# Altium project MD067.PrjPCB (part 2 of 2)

## Sheet MD067_INTERFACE.SchDoc
size 431 x 279 mm; Date: Not shown in title block; ApprovedBy: Not shown in title block; CheckedBy: Not shown in title block; Author: Not shown in title block; CompanyName: Not shown in title block; Engineer: Not shown in title block; Organization: Not shown in title block; Address1: Not shown in title block; Address2: Not shown in title block; Address3: Not shown in title block; Address4: Not shown in title block; DocumentNumber: 1; Revision: Use project parameter SCH_Rev; SheetNumber: 1; SheetTotal: 5; PageSetup: Record=PageOptions¦CenterHorizontal=True¦CenterVertical=True¦PrintScale=1.00¦XCorrection=1.00¦YCorrection=1.00¦PrintKind=0¦BorderSize=5000000¦LeftOffset=0¦BottomOffset=0¦Orientation=2¦PaperLength=1000¦PaperWidth=1000¦Scale=100¦PaperSource=15¦PrintQuality=600¦MediaType=1¦DitherType=10¦PaperKind=Letter¦PrintScaleMode=1
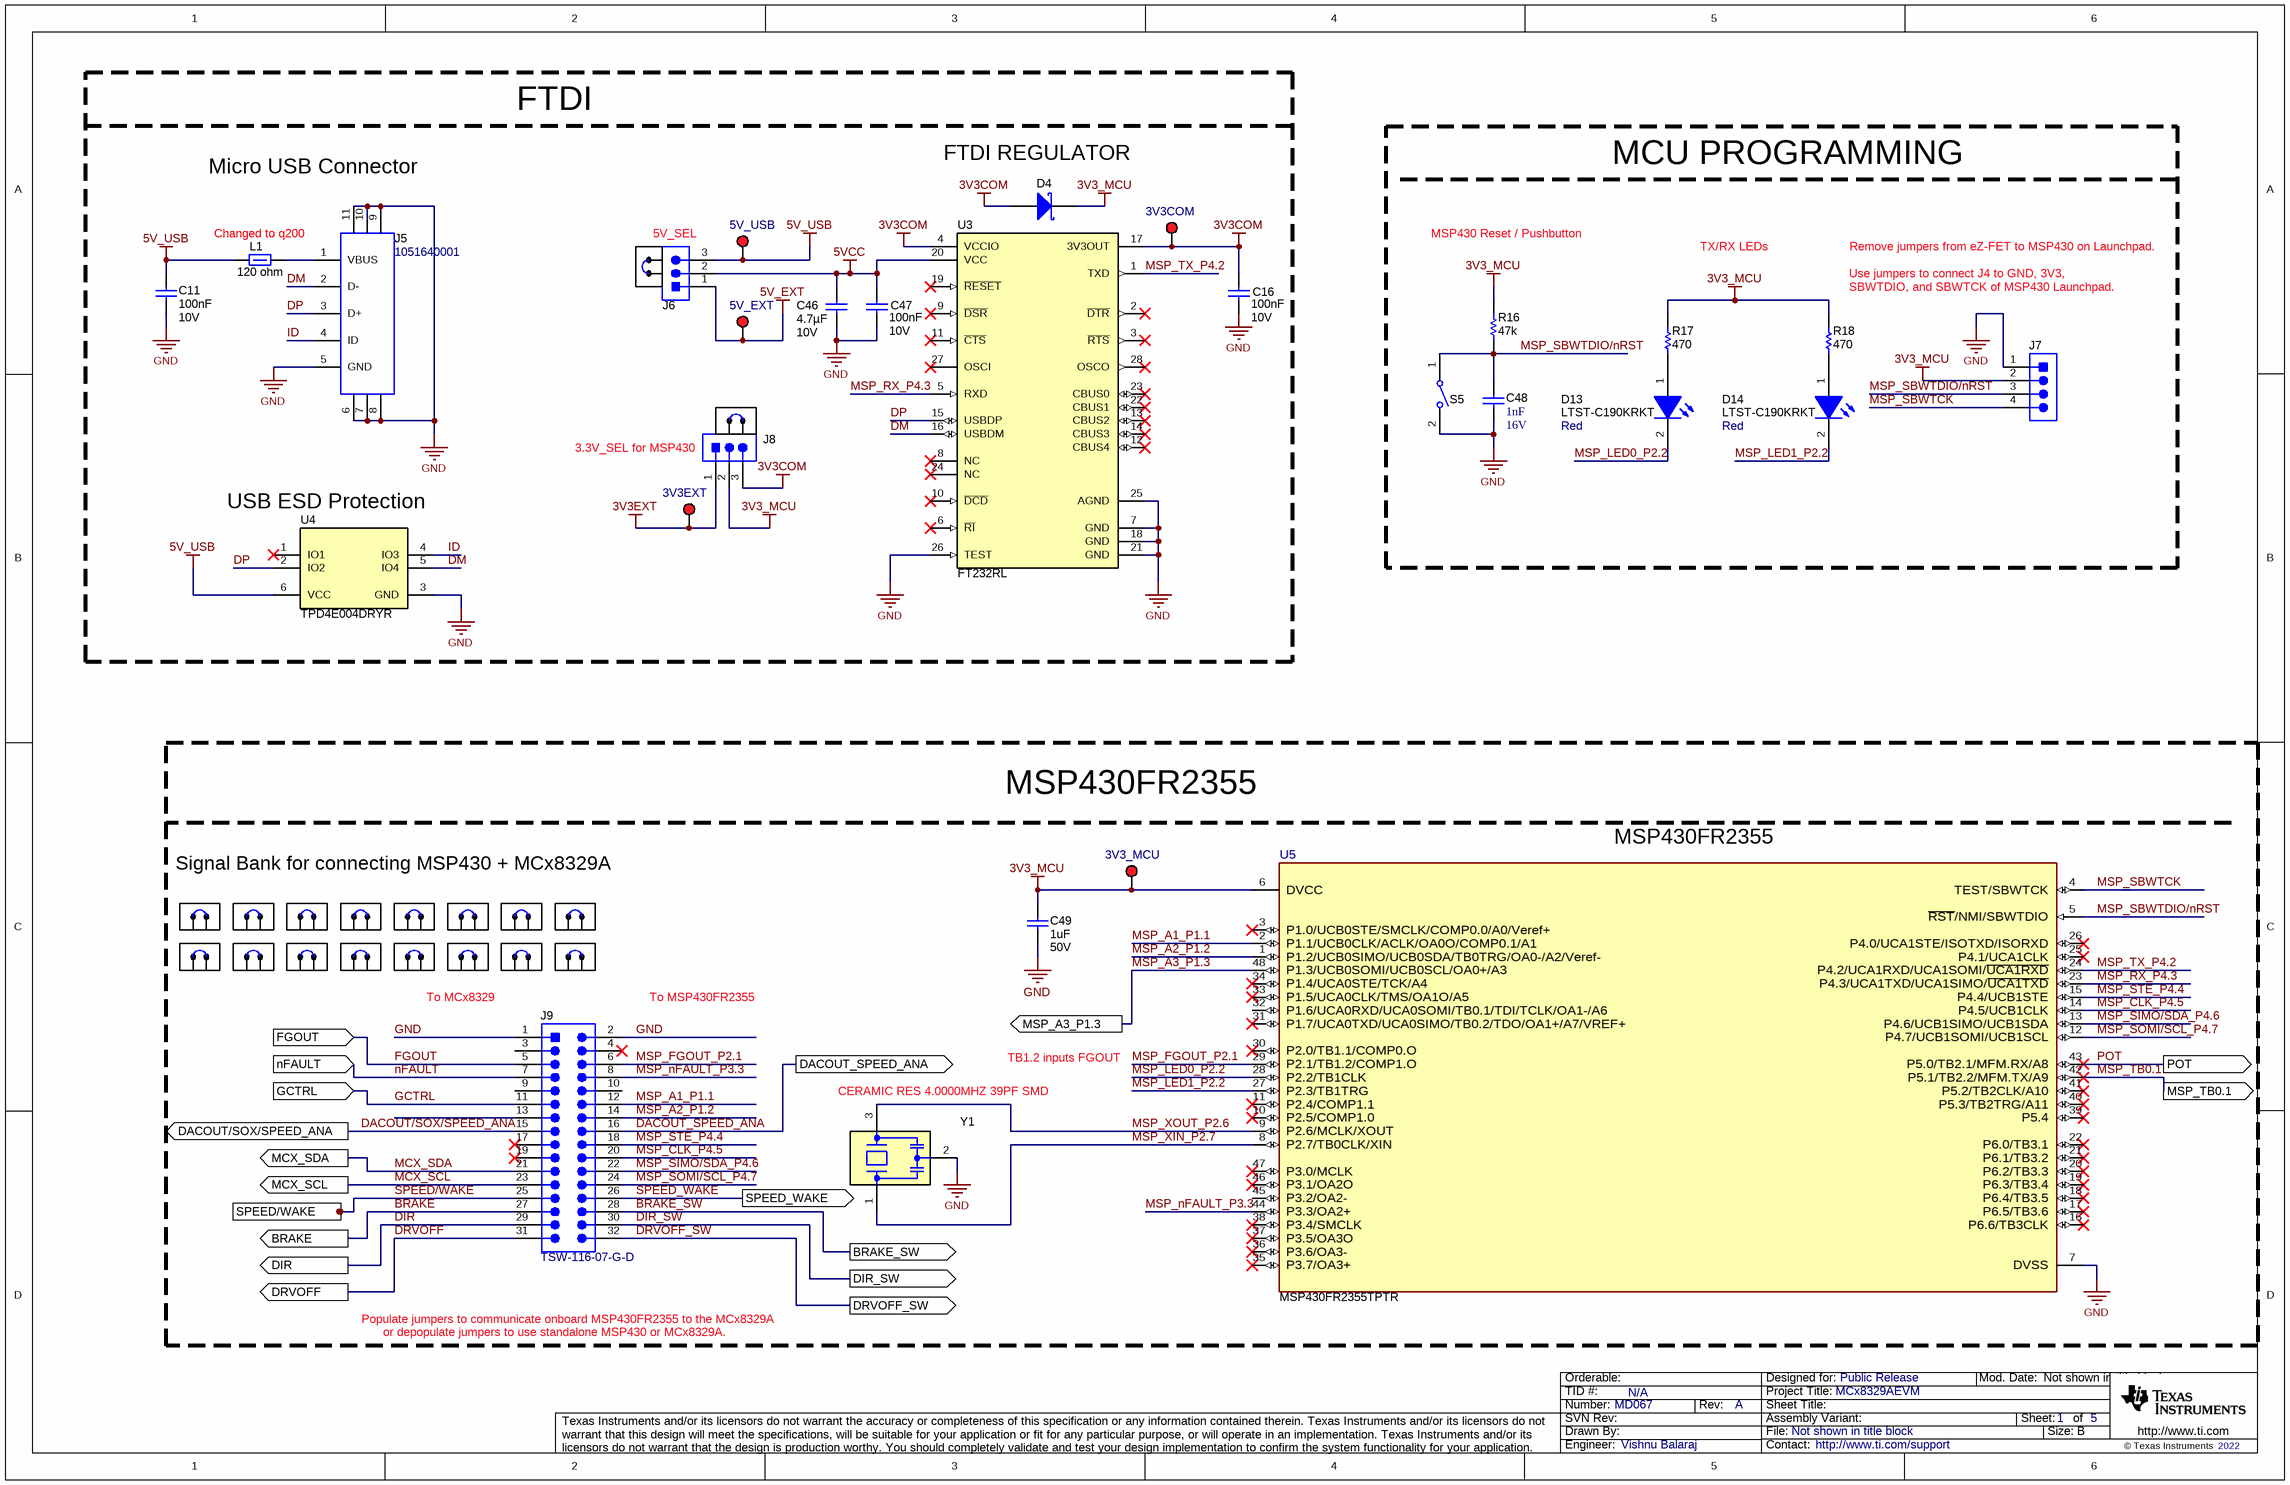
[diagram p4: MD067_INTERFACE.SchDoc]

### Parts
C11  Cap_F: 100nF  VDC_V: 10V  [0603L]  (hidden comment: 0603ZC104KAT2A)
C16  Cap_F: 100nF  VDC_V: 10V  [0603L]  (hidden comment: 0603ZC104KAT2A)
C46  Cap_F: 4.7µF  VDC_V: 10V  [0603L]  (hidden comment: GRM188Z71A475ME15D)
C47  Cap_F: 100nF  VDC_V: 10V  [0603L]  (hidden comment: 0603ZC104KAT2A)
C48  Cap_F: 1nF  VDC_V: 16V  [0603L]  (hidden comment: 885012206034)
C49  ValueDisplayed: 1uF  VDC_V: 50V  [0805L]  (hidden comment: 885012207103)
D4  BAT165E6327HTSA1  [SOD-323]  (value not drawn)
D13  LTST-C190KRKT  value Red  [LED_LTST-C190_Red]
D14  LTST-C190KRKT  value Red  [LED_LTST-C190_Red]
J5  1051640001  [Molex_1051640001]
J6  5V_SEL  [PBC03SAAN]  (value not drawn)
J7  TSW-104-07-G-S  [TSW-104-07-G-S]  (value not drawn)
J8  Header_3x1  [PBC03SAAN]  (value not drawn)
J9  TSW-116-07-G-D  [TSW-116-07-G-D]
L1  DCR_ohm: 120 ohm  [0603L]  (hidden comment: BLM18SG121TZ1D)
R16  ValueDisplayed: 47k  [0603L]  (hidden comment: RC0603JR-0747KL)
R17  ValueDisplayed: 470  [0603L]  (hidden comment: RC0603JR-07470RL)
R18  ValueDisplayed: 470  [0603L]  (hidden comment: RC0603JR-07470RL)
S5  SW_SPST-single  [SW_434121025816]  (value not drawn)
SH-J4  SNT-100-BK-G  [SNT-100-BK-G]  (value not drawn)
SH-J5  SNT-100-BK-G  [SNT-100-BK-G]  (value not drawn)
SH-J6  SNT-100-BK-G  [SNT-100-BK-G]  (value not drawn)
SH-J10  SNT-100-BK-G  [SNT-100-BK-G]  (value not drawn)
SH-J11  SNT-100-BK-G  [SNT-100-BK-G]  (value not drawn)
SH-J12  SNT-100-BK-G  [SNT-100-BK-G]  (value not drawn)
SH-J13  SNT-100-BK-G  [SNT-100-BK-G]  (value not drawn)
SH-J14  SNT-100-BK-G  [SNT-100-BK-G]  (value not drawn)
SH-J15  SNT-100-BK-G  [SNT-100-BK-G]  (value not drawn)
SH-J16  SNT-100-BK-G  [SNT-100-BK-G]  (value not drawn)
SH-J17  SNT-100-BK-G  [SNT-100-BK-G]  (value not drawn)
SH-J18  SNT-100-BK-G  [SNT-100-BK-G]  (value not drawn)
SH-J19  SNT-100-BK-G  [SNT-100-BK-G]  (value not drawn)
SH-J20  SNT-100-BK-G  [SNT-100-BK-G]  (value not drawn)
SH-J21  SNT-100-BK-G  [SNT-100-BK-G]  (value not drawn)
SH-J22  SNT-100-BK-G  [SNT-100-BK-G]  (value not drawn)
SH-J23  SNT-100-BK-G  [SNT-100-BK-G]  (value not drawn)
SH-J24  SNT-100-BK-G  [SNT-100-BK-G]  (value not drawn)
TP41  3V3COM  [Keystone5000]
TP42  5V_USB  [Keystone5000]
TP43  5V_EXT  [Keystone5000]
TP44  3V3EXT  [Keystone5000]
TP45  3V3_MCU  [Keystone5000]
U3  FT232RL  [SSOP28_N]
U4  TPD4E004DRYR  [DRY0006A]
U5  MSP430FR2355TPTR  [PT0048A-MFG]
Y1  CSTCR4M00G55B-R0  [Murata_CSTCR_G]  (value not drawn)

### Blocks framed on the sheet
FTDI: C11 C16 C46 C47 D4 J5 J6 J8 L1 SH-J4 SH-J5 TP41-TP44 U3 U4
MCU PROGRAMMING: C48 D13 D14 J7 R16-R18 S5
MSP430FR2355: C49 J9 SH-J6 SH-J10-SH-J24 TP45 U5 Y1

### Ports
BRAKE (out), BRAKE_SW (out), DACOUT/SOX/SPEED_ANA (out), DACOUT_SPEED_ANA (out), DIR (out), DIR_SW (out), DRVOFF (out), DRVOFF_SW (out), FGOUT (in), GCTRL (in), MCX_SCL (out), MCX_SDA (out), MSP_A3_P1.3 (out), MSP_TB0.1 (out), nFAULT (in), POT (out), SPEED/WAKE (out), SPEED_WAKE (out)

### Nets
3V3_MCU: C49.1 D4.1(K) J7.2 J8.2 R16.2 R17.2 R18.2 TP45.1 U5.6(DVCC)
3V3COM: C16.1 D4.2(A) J8.3 TP41.1 U3.4(VCCIO) U3.17(3V3OUT)
3V3EXT: J8.1 TP44.1
5V_EXT: J6.1 TP43.1
5V_USB: C11.1 J6.3 L1.1 TP42.1 U4.6(VCC)
5VCC: C46.2 C47.1 J6.2 U3.20(VCC)
GND: C11.2 C16.2 C46.1 C47.2 C48.2 C49.2 J5.5(GND) J5.6 J5.7 J5.8 J5.9 J5.10 J5.11 J7.1 J9.1 J9.2 S5.2 U3.7(GND) U3.18(GND) U3.21(GND) U3.25(AGND) U3.26(TEST) U4.3(GND) U5.7(DVSS) Y1.2(GND)
BRAKE: J9.27 ; port BRAKE
BRAKE_SW: J9.28 ; port BRAKE_SW
DACOUT/SOX/SPEED_ANA: J9.15 ; port DACOUT/SOX/SPEED_ANA
DACOUT_SPEED_ANA: J9.16 ; port DACOUT_SPEED_ANA
DIR: J9.29 ; port DIR
DIR_SW: J9.30 ; port DIR_SW
DM: J5.2(D-) U3.16(USBDM) U4.5(IO4)
DP: J5.3(D+) U3.15(USBDP) U4.2(IO2)
DRVOFF: J9.31 ; port DRVOFF
DRVOFF_SW: J9.32 ; port DRVOFF_SW
FGOUT: J9.5 ; port FGOUT
GCTRL: J9.11 ; port GCTRL
ID: J5.4(ID) U4.4(IO3)
MCX_SCL: J9.23 ; port MCX_SCL
MCX_SDA: J9.21 ; port MCX_SDA
MSP_A1_P1.1: J9.12 U5.2(P1.1/UCB0CLK/ACLK/OA0O/COMP0.1/A1)
MSP_A2_P1.2: J9.14 U5.1(P1.2/UCB0SIMO/UCB0SDA/TB0TRG/OA0-/A2/Veref-)
MSP_A3_P1.3: U5.48(P1.3/UCB0SOMI/UCB0SCL/OA0+/A3) ; port MSP_A3_P1.3
MSP_CLK_P4.5: J9.20 U5.14(P4.5/UCB1CLK)
MSP_FGOUT_P2.1: J9.6 U5.29(P2.1/TB1.2/COMP1.O)
MSP_LED0_P2.2: D13.2(K) U5.28(P2.2/TB1CLK)
MSP_LED1_P2.2: D14.2(K) U5.27(P2.3/TB1TRG)
MSP_nFAULT_P3.3: J9.8 U5.44(P3.3/OA2+)
MSP_RX_P4.3: U3.5(RXD) U5.23(P4.3/UCA1TXD/UCA1SIMO/~{UCA1TXD})
MSP_SBWTCK: J7.4 U5.4(TEST/SBWTCK)
MSP_SBWTDIO/nRST: C48.1 J7.3 R16.1 S5.1 U5.5(~{RST}/NMI/SBWTDIO)
MSP_SIMO/SDA_P4.6: J9.22 U5.13(P4.6/UCB1SIMO/UCB1SDA)
MSP_SOMI/SCL_P4.7: J9.24 U5.12(P4.7/UCB1SOMI/UCB1SCL)
MSP_STE_P4.4: J9.18 U5.15(P4.4/UCB1STE)
MSP_TB0.1: U5.42(P5.1/TB2.2/MFM.TX/A9) ; port MSP_TB0.1
MSP_TX_P4.2: U3.1(TXD) U5.24(P4.2/UCA1RXD/UCA1SOMI/~{UCA1RXD})
MSP_XIN_P2.7: U5.8(P2.7/TB0CLK/XIN) Y1.1(In)
MSP_XOUT_P2.6: U5.9(P2.6/MCLK/XOUT) Y1.3(Out)
nFAULT: J9.7 ; port nFAULT
POT: U5.43(P5.0/TB2.1/MFM.RX/A8) ; port POT
SPEED/WAKE: J9.25 ; port SPEED/WAKE
SPEED_WAKE: J9.26 ; port SPEED_WAKE
NetD13_1: D13.1(A) R17.1
NetD14_1: D14.1(A) R18.1
NetJ5_1: J5.1(VBUS) L1.2

Not connected (* = marked no-connect by the designer): J9 3 4* 9 10 13 17* 19*; U3 2(~{DTR})* 3(~{RTS})* 6(~{RI})* 8(NC)* 9(~{DSR})* 10(~{DCD})* 11(~{CTS})* 12(CBUS4)* 13(CBUS2)* 14(CBUS3)* 19(~{RESET})* 22(CBUS1)* 23(CBUS0)* 24(NC)* 27(OSCI)* 28(OSCO)*; U4 1(IO1)*; U5 3(P1.0/UCB0STE/SMCLK/COMP0.0/A0/Veref+)* 10(P2.5/COMP1.0)* 11(P2.4/COMP1.1)* 16(P6.6/TB3CLK)* 17(P6.5/TB3.6)* 18(P6.4/TB3.5)* 19(P6.3/TB3.4)* 20(P6.2/TB3.3)* 21(P6.1/TB3.2)* 22(P6.0/TB3.1)* 25(P4.1/UCA1CLK)* 26(P4.0/UCA1STE/ISOTXD/ISORXD)* 30(P2.0/TB1.1/COMP0.O)* 31(P1.7/UCA0TXD/UCA0SIMO/TB0.2/TDO/OA1+/A7/VREF+)* 32(P1.6/UCA0RXD/UCA0SOMI/TB0.1/TDI/TCLK/OA1-/A6) 33(P1.5/UCA0CLK/TMS/OA1O/A5)* 34(P1.4/UCA0STE/TCK/A4)* 35(P3.7/OA3+)* 36(P3.6/OA3-)* 37(P3.5/OA3O)* 38(P3.4/SMCLK)* 39(P5.4)* 40(P5.3/TB2TRG/A11)* 41(P5.2/TB2CLK/A10)* 45(P3.2/OA2-) 46(P3.1/OA2O)* 47(P3.0/MCLK)*

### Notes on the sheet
- Micro USB Connector
- (near D4) FTDI REGULATOR
- (near L1) Changed to q200
- 5V_SEL
- MSP430 Reset / Pushbutton
- TX/RX LEDs
- (near R18) Use jumpers to connect J4 to GND, 3V3,
- SBWTDIO, and SBWTCK of MSP430 Launchpad.
- Remove jumpers from eZ-FET to MSP430 on Launchpad.
- (near U4) USB ESD Protection
- (near J8) 3.3V_SEL for MSP430
- (near U5) MSP430FR2355
- Signal Bank for connecting MSP430 + MCx8329A
- To MCx8329
- To MSP430FR2355
- (near Y1) CERAMIC RES 4.0000MHZ 39PF SMD
- TB1.2 inputs FGOUT
- or depopulate jumpers to use standalone MSP430 or MCx8329A.
- Populate jumpers to communicate onboard MSP430FR2355 to the MCx8329A

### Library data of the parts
C11 C16 C47 = CMP-0006815-4: CAP, CERM, 0.1 uF, 10 V, +/- 10%, X7R, 0603; Manufacturer: AVX; TaMin_C: -55°C; Polarized: N; SizeAreaWB_mm2: 4.68; Value1: Unknown; U/M: EA; Value: 0.1uF; TaMax_C: 125°C; SizeZ_mm: 1; SizeX_mm: 1.6; SizeY_mm: 0.8; Cap_Case: 0603; SizeArea_mm2: 1.28; AEC Category: Q200
C46 = CMP-0007498-4: CAP, CERM, 4.7 uF, 10 V, +/- 20%, X7R, 0603; Manufacturer: MuRata; TaMin_C: -55°C; Polarized: N; SizeAreaWB_mm2: 4.68; Value1: Unknown; U/M: EA; Value: 4.7uF; TaMax_C: 125°C; SizeZ_mm: 1; SizeX_mm: 1.6; SizeY_mm: 0.8; Cap_Case: 0603; SizeArea_mm2: 1.28; AEC Category: Q200
C48 = CMP-0006826-4: CAP, CERM, 1000 pF, 16 V, +/- 10%, X7R, 0603; Manufacturer: Wurth Elektronik; TaMin_C: -55°C; Polarized: N; SizeAreaWB_mm2: 4.68; Value1: Unknown; U/M: EA; Value: 1000pF; TaMax_C: 125°C; SizeZ_mm: 1; SizeX_mm: 1.6; SizeY_mm: 0.8; Cap_Case: 0603; SizeArea_mm2: 1.28; AEC Category: Q200
C49 = CMP-0007696-2: CAP, CERM, 1 uF, 50 V, +/- 10%, X7R, 0805; Manufacturer: Wurth Elektronik; Polarized: N; CompType: Capacitor; Value: 1uF; U/M: EA; Cap_F: 1µF; Value1: Unknown; TaMin_C: -55°C; TaMax_C: 125°C; Cap_Case: 0805; SizeArea_mm2: 2.5; SizeAreaWB_mm2: 6.75; SizeX_mm: 2; SizeY_mm: 1.25; SizeZ_mm: 1.45; AEC Category: Q200
D4 = CMP-0028882-2: Diode, Schottky, 40 V, 0.75 A, AEC-Q101, SOD-323; Manufacturer: Infineon Technologies; Vf_V: 740mV; Value: 40V; Value1: 0.75A; Value2: 0.74V; Io_A: 750mA; TJmax_C: 150°C; AEC Category: Q101; AEC Qualified: Y; Green_Lifecycle: Not Set; Green_REACh: Incomplete; SizeArea_mm2: 3.645; SizeAreaWB_mm2: 8.695; SizeX_mm: 2.7; SizeY_mm: 1.35; SizeZ_mm: 1
D13 D14 = CMP-0078131-2: LED, Red, SMD; Manufacturer: Lite-On; Type: AlInGaP; Ir_A: 10µA; Angle: 130; Power_TotalModule: 62.5mW; Value2: 2V; Green_Lifecycle: Not Set; Io_A: 20mA; Value1: .0625W; Green_REACh: Incomplete; Vr_V: 5V
J5 = CMP-0055311-1: Receptacle, USB 2.0, Micro B, 5 Position, R/A, SMT; Manufacturer: Molex; CNHeader: FALSE; Current_A: 1.8A; Gender: Female; Voltage_V: 30V; Pitch_mm: 0.65; ContactFinish: Gold; CT: TRUE; Cert_UL: Y
J6 J8 = CMP-0002334-1: Header, 100mil, 3x1, Gold, TH; Manufacturer: Sullins Connector Solutions; CNHeader: TRUE; CT: FALSE; Green_Lifecycle: Not Set; Green_REACh: Incomplete
J7 = CMP-0075409-2: Header, 100mil, 4x1, Gold, TH; Manufacturer: Samtec; Pitch_mm: 2.54; Cert_VDE: N; Gender: Male; Cert_CSA: Y; Voltage_V: 550V; Green_REACh: Passed; Current_A: 6.3A; Green_Lifecycle: Active; Row_Count: 1
J9 = CMP-0075429-1: Header, 100mil, 16x2, Gold, TH; Manufacturer: Samtec; Pitch_mm: 2.54; Cert_VDE: N; Gender: Male; Cert_CSA: Y; Voltage_V: 550V; Green_REACh: Passed; Current_A: 6.3A; CT: False; Green_Lifecycle: Active; Row_Count: 2; CNHeader: True
L1 = CMP-0084877-1: Inductor, Ferrite Bead, Ferrite, 3 A, 120 ohm, AEC-Q200 Grade 1, SMD; Manufacturer: MuRata; SizeX_mm: 1.6; AEC Grade: 1; Value2: 3A; SizeY_mm: 0.8; SizeAreaWB_mm2: 4.68; SizeArea_mm2: 1.28; AEC Qualified: Y; AEC Category: Q200
R16 = CMP-0025925-5: RES, 47 k, 5%, 0.1 W, 0603; Manufacturer: Yageo; Power_W: 100mW; TempCo: 100 ppm/C; Value_Code: 47k0; Value: 47k; EIA_Code: E24; SizeX_mm: 1.6; SizeY_mm: 0.8; SizeZ_mm: 1; Value2: 0.1W; SizeArea_mm2: 1.28; AEC Qualified: N; VDC_V: 75V; AEC Category: Q200; SizeAreaWB_mm2: 4.68
R17 R18 = CMP-0025924-5: RES, 470, 5%, 0.1 W, 0603; Manufacturer: Yageo; Power_W: 100mW; TempCo: 100 ppm/C; Value_Code: 470R; Value: 470; EIA_Code: E24; SizeX_mm: 1.6; SizeY_mm: 0.8; SizeZ_mm: 1; Value2: 0.1W; SizeArea_mm2: 1.28; AEC Qualified: N; VDC_V: 75V; AEC Category: Q200; SizeAreaWB_mm2: 4.68
S5 = CMP-0002196-2: Switch, Tactile, SPST, 12 V, SMD; PartNumber: 434121025816; Manufacturer: Wurth Elektronik; VDC_V: 12V; SwitchFunction: Off-On; PositionCount: 1; CurrentRating_mA: 50A
SH-J4-SH-J6 SH-J10-SH-J24 = CMP-0003623-3: Shunt, 100mil, Gold plated, Black; Alternate PartNumber: 969102-0000-DA; Manufacturer: Samtec; Alternate Manufacturer: 3M; Value: 1x2
TP41-TP45 = CMP-0055137-1: Test Point, Miniature, Red, TH; PartNumber: 5000; Manufacturer: Keystone; ContactFinish: Silver; CNHeader: FALSE; CT: TRUE; Green_Lifecycle: Active; Green_REACh: Passed
U3 = CMP-0004774-1: USB to Serial UART, SSOP28; Manufacturer: FTDI
U4 = CMP-0043115-3: 4-Channel ESD Protection Array for High-Speed Data Interfaces, DRY0006A (USON-6); Manufacturer: Texas Instruments; IO Leakage Current(nA): 1; USB High Speed: TRUE; IO Capacitance(Typ)(pF): 1.6; Eco-Plan: Green (RoHS & no Sb/Br); IEC 61000-4-2 Contact(+/- kV): 8; Breakdown Voltage(Min)(V): 6; IEC 61000-4-2 Air-Gap(+/- kV): 12; AEC Category: Q200; AEC Qualified: N; CompType: IC; SizeAreaWB_mm2: 4.9; SizeArea_mm2: 1.45; SizeX_mm: 1.0; SizeZ_mm: 0.6; Rating: Catalog
U5 = CMP-0089204-1: CPU16 MSP430™ FRAM Microcontroller IC 16-Bit 24MHz 32KB (32K x 8) FRAM 48-LQFP (7x7); Manufacturer: Texas Instruments; Memory Type: OTHER; Data Bus Width: 16bits; Number Of Spi Channels: 4; Number Of I/Os: 44; Number Of Uart Channels: 2; AEC Qualified: No; Standoff Height: 0.05mm; Ram Size: 4KBytes; TaMin_C: -40°C; Core Architecture: RISC; Number Of Adc Channels: 12; SizeZ_mm: 1.6mm; Number Of A/D Converters: 1; Memory Size: 32KBytes; TaMax_C: +105°C; TJmax_C: +115°C; Interface: I2C,SPI,UART,USART,SCI,IrDA; Min Supply Voltage: 1.8V; Max Supply Voltage: 3.6V
Y1 = CMP-0084387-1: Resonator, 4 MHz, 39 pF, AEC-Q200 Grade 1, SMD; Manufacturer: MuRata; Load Capacitance: 39 pF; AEC Qualified: Y; TaMax_C: 125°C; AEC Category: Q200; SizeArea_mm2: 9; SizeZ_mm: 1.2; Frequency_Fixed: 4MHz; SizeAreaWB_mm2: 16.5; SizeY_mm: 2; SizeX_mm: 4.5; TaMin_C: -40°C; AEC Grade: 1

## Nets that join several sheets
AVDD: MD067_DRIVER (10 pins), MD067_POWER_AND_CONNECTORS (6 pins)
GND: MD067_DRIVER (23 pins), MD067_FETS_AND_POWER_STAGE (7 pins), MD067_POWER_AND_CONNECTORS (22 pins), MD067_INTERFACE (25 pins)
LSS: MD067_DRIVER (J4.14 TP9.1 U1.21), MD067_FETS_AND_POWER_STAGE (17 pins)
PVDD: MD067_DRIVER (5 pins), MD067_FETS_AND_POWER_STAGE (12 pins), MD067_POWER_AND_CONNECTORS (5 pins)
VREG: MD067_DRIVER (C37.1 C38.1 U1.2), MD067_POWER_AND_CONNECTORS (J12.1 J12.3 J12.5)
BRAKE: MD067_DRIVER (U1.34), MD067_INTERFACE (J9.27)
BRAKE_SW: MD067_POWER_AND_CONNECTORS (S1.2 TP26.1), MD067_INTERFACE (J9.28)
DACOUT/SOX/SPEED_ANA: MD067_DRIVER (R3.1 TP2.1 U1.33), MD067_INTERFACE (J9.15)
DACOUT_SPEED_ANA: MD067_POWER_AND_CONNECTORS (SW1.5), MD067_INTERFACE (J9.16)
DIR: MD067_DRIVER (R6.1 U1.31), MD067_INTERFACE (J9.29)
DIR_SW: MD067_POWER_AND_CONNECTORS (S3.2 TP32.1), MD067_INTERFACE (J9.30)
DRVOFF: MD067_DRIVER (U1.24), MD067_INTERFACE (J9.31)
DRVOFF_SW: MD067_POWER_AND_CONNECTORS (S2.2 TP31.1), MD067_INTERFACE (J9.32)
FGOUT: MD067_DRIVER (R8.1 TP4.1 U1.28), MD067_INTERFACE (J9.5)
GCTRL: MD067_DRIVER (TP5.1 U1.3), MD067_POWER_AND_CONNECTORS (R56.1), MD067_INTERFACE (J9.11)
GHA: MD067_DRIVER (J4.4 U1.11), MD067_FETS_AND_POWER_STAGE (R28.1 R31.1)
GHB: MD067_DRIVER (J4.8 U1.15), MD067_FETS_AND_POWER_STAGE (R29.1 R32.1)
GHC: MD067_DRIVER (J4.12 U1.19), MD067_FETS_AND_POWER_STAGE (R30.1 R33.1)
GLA: MD067_DRIVER (J4.5 U1.12), MD067_FETS_AND_POWER_STAGE (R34.1 R37.1)
GLB: MD067_DRIVER (J4.9 U1.16), MD067_FETS_AND_POWER_STAGE (R35.1 R38.1)
GLC: MD067_DRIVER (J4.13 U1.20), MD067_FETS_AND_POWER_STAGE (R36.1 R39.1)
MCX_SCL: MD067_DRIVER (R9.1 R11.1), MD067_INTERFACE (J9.23)
MCX_SDA: MD067_DRIVER (R10.1 R12.1), MD067_INTERFACE (J9.21)
MSP_A3_P1.3: MD067_POWER_AND_CONNECTORS (SW1.4), MD067_INTERFACE (U5.48)
MSP_TB0.1: MD067_POWER_AND_CONNECTORS (J13.6), MD067_INTERFACE (U5.42)
nFAULT: MD067_DRIVER (R5.1 R7.2 R14.1 U1.35), MD067_INTERFACE (J9.7)
OUTA: MD067_FETS_AND_POWER_STAGE (7 pins), MD067_POWER_AND_CONNECTORS (J11.1 TP27.1)
OUTB: MD067_FETS_AND_POWER_STAGE (7 pins), MD067_POWER_AND_CONNECTORS (J11.2 TP28.1)
OUTC: MD067_FETS_AND_POWER_STAGE (7 pins), MD067_POWER_AND_CONNECTORS (J11.3 TP29.1)
POT: MD067_POWER_AND_CONNECTORS (C36.1 J13.4 R54.1 SW1.6), MD067_INTERFACE (U5.43)
SHA: MD067_DRIVER (C8.1 J4.3 U1.10), MD067_FETS_AND_POWER_STAGE (NT1.1)
SHB: MD067_DRIVER (C9.2 J4.7 U1.14), MD067_FETS_AND_POWER_STAGE (NT2.1)
SHC: MD067_DRIVER (C10.2 J4.11 U1.18), MD067_FETS_AND_POWER_STAGE (NT3.1)
SN: MD067_DRIVER (TP39.1 U1.23), MD067_FETS_AND_POWER_STAGE (C31.2 C32.1 R45.1)
SP: MD067_DRIVER (TP11.1 U1.22), MD067_FETS_AND_POWER_STAGE (C30.2 C31.1 R43.1)
SPEED/WAKE: MD067_DRIVER (R51.2 U1.27), MD067_INTERFACE (J9.25)
SPEED_WAKE: MD067_POWER_AND_CONNECTORS (SW1.2), MD067_INTERFACE (J9.26)

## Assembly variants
001: not fitted C12 C13 C14 C15 C17 C19 C24 C25 C26 C27 C28 C29 C30 C31 C32 D5 D6 D7 D8 D9 D10 FID1 FID2 FID3 R1 R2 R3 R4 R5 R6 R22 R25 R26 R27 R31 R32 R33 R37 R38 R39 R40 R41 R42 R50 R51 R60 R75 R76 R77 R78
002: not fitted C12 C13 C14 C15 C17 C19 C24 C25 C26 C27 C28 C29 C30 C31 C32 D5 D6 D7 D8 D9 D10 FID1 FID2 FID3 R1 R2 R3 R4 R5 R6 R11 R12 R14 R17 R18 R19 R20 R21 R22 R25 R26 R27 R31 R32 R33 R37 R38 R39 R40 R41 R42 R46 R50 R51 R60 R75 R76 R77 R78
